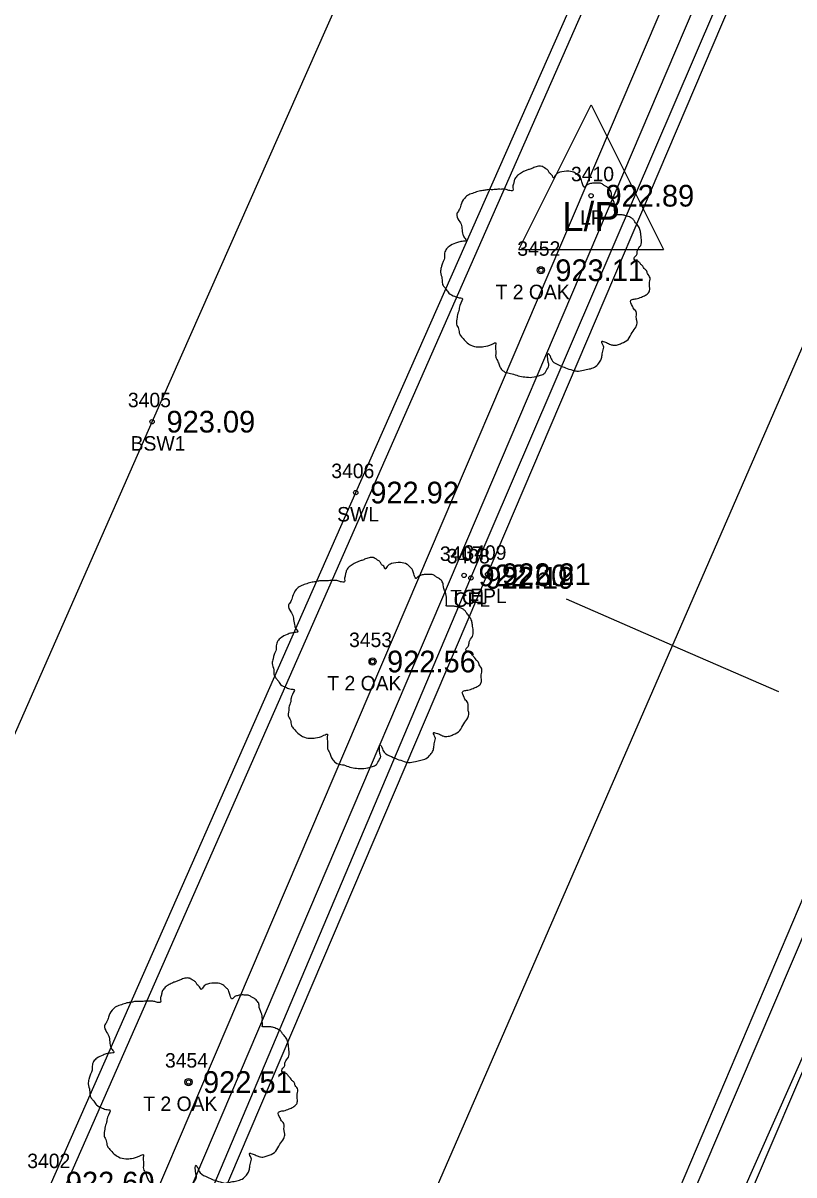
# Model space of a CAD drawing. Extents: x 1575382 to 1578175, y 1099175 to 1101955.
# Drawn here: x 1577107.7 to 1577161, y 1100867.9 to 1100947.5 of the extents above; entities that cross this region are included whole.
import ezdxf

# ---------------------------------------------------------------- set-up
doc = ezdxf.new("R2010")
doc.units = 0
for name, color, linetype in [('RD_EX_Conc', 7, 'Continuous'), ('RD_EX_Conc_txCode', 7, 'Continuous'), ('RD_EX_DR_Pipe', 7, 'Continuous'), ('RD_EX_Road', 7, 'Continuous'), ('RD_EX_Road_txCode', 7, 'Continuous'), ('RD_EX_TX_Conc_ELEV', 7, 'Continuous'), ('RD_EX_TX_Road_ELEV', 7, 'Continuous'), ('RD_EX_TX_UT_ELEV', 7, 'Continuous'), ('RD_EX_TX_VEG_ELEV', 7, 'Continuous'), ('RD_EX_UT', 7, 'Continuous'), ('RD_EX_UT_txCode', 7, 'Continuous'), ('RD_EX_VEG', 7, 'Continuous'), ('RD_EX_VEG_txCode', 7, 'Continuous'), ('RD_HC_Cl', 7, 'Continuous'), ('RD_HC_Data_Tic', 7, 'Continuous'), ('RD_SMD_Locator', 7, 'Continuous')]:
    doc.layers.add(name, color=color, linetype=linetype)

msp = doc.modelspace()

# ---------------------------------------------------------------- linework, layer by layer
at = {"layer": 'RD_EX_Conc'}
for points in [[(1577067.37, 1100812.254), (1577083.485, 1100844.878), (1577096.643, 1100874.508), (1577116.651, 1100919.942), (1577136.82, 1100965.443), (1577156.654, 1101010.405), (1577183.297, 1101070.643)], [(1577079.252, 1100805.075), (1577097.111, 1100838.835), (1577109.69, 1100867.343), (1577130.743, 1100915.042), (1577150.176, 1100959.002), (1577170.082, 1101003.92), (1577196.775, 1101064.656), (1577202.486, 1101060.003)], [(1577107.978, 1100836.943), (1577119.094, 1100862.854), (1577138.707, 1100909.145), (1577158.456, 1100955.145), (1577177.696, 1100999.964), (1577190.709, 1101030.459)], [(1577129.98, 1100812.481), (1577147.365, 1100850.909), (1577167.052, 1100896.938), (1577173.888, 1100913.381)], [(1577132.717, 1100811.321), (1577150.445, 1100848.795), (1577170.285, 1100895.209), (1577174.895, 1100906.424), (1577174.458, 1100913.152)]]:
    msp.add_lwpolyline(points, dxfattribs=at)
at = {"layer": 'RD_EX_DR_Pipe'}
for points in [[(1577226.312, 1101118.81), (1577219.842, 1101092.631), (1577219.842, 1101092.631), (1577205.279, 1101049.599), (1577205.279, 1101049.599), (1577188.031, 1101033.131), (1577188.031, 1101033.131), (1577101.879, 1100831.452)], [(1577139.994, 1100787.337), (1577129.779, 1100804.197), (1577129.779, 1100804.197), (1577232.824, 1101036.463), (1577232.824, 1101036.463), (1577240.152, 1101052.982)]]:
    msp.add_lwpolyline(points, dxfattribs=at)
at = {"layer": 'RD_EX_Road'}
for points in [[(1577060.606, 1100805.432), (1577075.531, 1100798.536), (1577081.931, 1100797.671), (1577087.923, 1100798.374), (1577091.212, 1100799.398), (1577094.487, 1100804.268), (1577106.896, 1100832.158), (1577119.895, 1100862.619), (1577139.857, 1100909.397), (1577159.206, 1100954.774), (1577178.498, 1100999.731), (1577192.432, 1101032.313), (1577206.431, 1101064.716)], [(1577078.765, 1100718.331), (1577101.643, 1100758.923), (1577113.339, 1100780.089), (1577125.29, 1100804.69), (1577146.474, 1100851.246), (1577166.057, 1100897.319), (1577205.167, 1100988.676), (1577222.285, 1101028.955), (1577224.552, 1101032.022), (1577228.298, 1101034.471), (1577233.178, 1101036.099), (1577233.178, 1101036.099), (1577237.423, 1101035.839), (1577245.428, 1101032.846), (1577248.283, 1101031.553), (1577256.851, 1101026.156), (1577298.2, 1100997.596), (1577319.207, 1100982.295), (1577334.075, 1100971.377)]]:
    msp.add_lwpolyline(points, dxfattribs=at)
at = {"layer": 'RD_EX_UT'}
for p, q in [((1577142.014, 1100931.838), (1577147.014, 1100941.838)), ((1577147.014, 1100941.838), (1577152.014, 1100931.838)), ((1577142.014, 1100931.838), (1577152.014, 1100931.838))]:
    msp.add_line(p, q, dxfattribs=at)
at = {"layer": 'RD_EX_VEG'}
msp.add_lwpolyline([(1577107.032, 1100838.114), (1577102.407, 1100840.005), (1577098.784, 1100830.652), (1577102.641, 1100828.563), (1577091.872, 1100804.274), (1577078.023, 1100800.1), (1577101.108, 1100845.444), (1577197.024, 1101063.208), (1577201.438, 1101059.636), (1577191.641, 1101036.576), (1577187.356, 1101037.816), (1577185.071, 1101032.424), (1577189.095, 1101030.587), (1577107.032, 1100838.114)], dxfattribs=at)
for centre, radius in [((1577143.545, 1100930.411), 0.25), ((1577143.532, 1100930.392), 0.0001), ((1577131.908, 1100903.363), 0.25), ((1577131.896, 1100903.344), 0.0001), ((1577119.176, 1100874.292), 0.25), ((1577119.164, 1100874.273), 0.0001)]:
    msp.add_circle(centre, radius, dxfattribs=at)
for points in [[(1577143.677, 1100937.579), (1577143.377, 1100937.604), (1577143.052, 1100937.504), (1577142.802, 1100937.404), (1577142.577, 1100937.329), (1577142.352, 1100937.229), (1577142.052, 1100937.054), (1577141.827, 1100936.854), (1577141.702, 1100936.604), (1577141.652, 1100936.379), (1577141.602, 1100936.104), (1577141.602, 1100935.929), (1577141.478, 1100935.904), (1577141.328, 1100935.929), (1577141.078, 1100936.004), (1577140.828, 1100936.004), (1577140.578, 1100936.004), (1577140.228, 1100935.979), (1577139.878, 1100935.979), (1577139.603, 1100935.929), (1577139.278, 1100935.879), (1577138.904, 1100935.754), (1577138.554, 1100935.629), (1577138.254, 1100935.379), (1577138.004, 1100934.905), (1577137.879, 1100934.555), (1577137.729, 1100934.305), (1577137.879, 1100933.855), (1577138.054, 1100933.505), (1577138.079, 1100933.305), (1577138.154, 1100932.881), (1577138.254, 1100932.656), (1577138.379, 1100932.456), (1577138.304, 1100932.431), (1577137.929, 1100932.381), (1577137.629, 1100932.281), (1577137.204, 1100932.056), (1577136.979, 1100931.831), (1577136.879, 1100931.506), (1577136.855, 1100931.156), (1577136.755, 1100930.956), (1577136.68, 1100930.682), (1577136.655, 1100930.607), (1577136.605, 1100930.282), (1577136.705, 1100929.832), (1577136.73, 1100929.482), (1577136.855, 1100929.257), (1577137.004, 1100929.082), (1577137.179, 1100928.832), (1577137.579, 1100928.607), (1577137.904, 1100928.507), (1577138.104, 1100928.483), (1577137.929, 1100927.983), (1577137.879, 1100927.633), (1577137.754, 1100927.233), (1577137.754, 1100927.158), (1577137.704, 1100926.683), (1577137.854, 1100926.358), (1577137.929, 1100925.984), (1577138.104, 1100925.759), (1577138.379, 1100925.459), (1577138.704, 1100925.234), (1577139.204, 1100925.109), (1577139.603, 1100925.134), (1577140.178, 1100925.309), (1577140.428, 1100925.384), (1577140.403, 1100925.209), (1577140.428, 1100924.834), (1577140.428, 1100924.409), (1577140.578, 1100924.084), (1577140.678, 1100923.81), (1577140.828, 1100923.56), (1577141.153, 1100923.335), (1577141.552, 1100923.26), (1577141.977, 1100923.11), (1577142.427, 1100923.035), (1577142.927, 1100923.01), (1577143.527, 1100923.16), (1577143.801, 1100923.285), (1577143.901, 1100923.46), (1577144.101, 1100923.835), (1577144.051, 1100924.059), (1577144.076, 1100924.659), (1577144.176, 1100924.484), (1577144.351, 1100924.134), (1577144.851, 1100923.835), (1577145.251, 1100923.66), (1577145.726, 1100923.51), (1577146.026, 1100923.435), (1577146.5, 1100923.51), (1577146.875, 1100923.585), (1577147.25, 1100923.71), (1577147.55, 1100923.984), (1577147.725, 1100924.259), (1577147.775, 1100924.534), (1577147.85, 1100924.909), (1577147.9, 1100925.084)], [(1577147.9, 1100925.084), (1577147.825, 1100925.259), (1577147.775, 1100925.509), (1577147.85, 1100925.484), (1577148.025, 1100925.434), (1577148.3, 1100925.309), (1577148.524, 1100925.234), (1577148.849, 1100925.259), (1577149.124, 1100925.359), (1577149.574, 1100925.634), (1577149.849, 1100926.109), (1577150.124, 1100926.508), (1577150.199, 1100926.833), (1577150.149, 1100927.058), (1577150.124, 1100927.558), (1577149.924, 1100927.808), (1577149.874, 1100927.933), (1577149.774, 1100928.333), (1577149.849, 1100928.383), (1577150.124, 1100928.433), (1577150.499, 1100928.557), (1577150.773, 1100928.682), (1577150.998, 1100928.857), (1577151.073, 1100929.082), (1577151.048, 1100929.482), (1577151.098, 1100929.882), (1577151.023, 1100930.032), (1577150.923, 1100930.182), (1577150.848, 1100930.382), (1577150.698, 1100930.532), (1577150.599, 1100930.682), (1577150.499, 1100930.781), (1577150.374, 1100930.931), (1577150.199, 1100931.056), (1577150.049, 1100931.106), (1577149.999, 1100931.256), (1577150.149, 1100931.456), (1577150.199, 1100931.556), (1577150.224, 1100931.781), (1577150.449, 1100932.131), (1577150.499, 1100932.531), (1577150.449, 1100932.956), (1577150.399, 1100933.23), (1577150.249, 1100933.505), (1577150.049, 1100933.755), (1577149.924, 1100933.93), (1577149.749, 1100934.055), (1577149.424, 1100934.18), (1577149.174, 1100934.23), (1577148.824, 1100934.23), (1577148.624, 1100934.28), (1577148.649, 1100934.33), (1577148.649, 1100934.48), (1577148.649, 1100934.755), (1577148.574, 1100935.205), (1577148.424, 1100935.704), (1577148.424, 1100935.729), (1577148.324, 1100935.979), (1577148.1, 1100936.179), (1577147.925, 1100936.279), (1577147.725, 1100936.404), (1577147.475, 1100936.429), (1577147.175, 1100936.429), (1577146.9, 1100936.379), (1577146.7, 1100936.279), (1577146.525, 1100936.154), (1577146.45, 1100936.304), (1577146.35, 1100936.604), (1577146.3, 1100936.754), (1577146.15, 1100936.929), (1577145.926, 1100937.129), (1577145.476, 1100937.254), (1577144.851, 1100937.179), (1577144.551, 1100936.979), (1577144.401, 1100936.804), (1577144.351, 1100936.929), (1577144.151, 1100937.129), (1577144.051, 1100937.304), (1577143.876, 1100937.429), (1577143.727, 1100937.529), (1577143.627, 1100937.579)], [(1577132.04, 1100910.53), (1577131.74, 1100910.555), (1577131.416, 1100910.455), (1577131.166, 1100910.355), (1577130.941, 1100910.28), (1577130.716, 1100910.18), (1577130.416, 1100910.005), (1577130.191, 1100909.806), (1577130.066, 1100909.556), (1577130.016, 1100909.331), (1577129.966, 1100909.056), (1577129.966, 1100908.881), (1577129.841, 1100908.856), (1577129.691, 1100908.881), (1577129.441, 1100908.956), (1577129.192, 1100908.956), (1577128.942, 1100908.956), (1577128.592, 1100908.931), (1577128.242, 1100908.931), (1577127.967, 1100908.881), (1577127.642, 1100908.831), (1577127.267, 1100908.706), (1577126.918, 1100908.581), (1577126.618, 1100908.331), (1577126.368, 1100907.856), (1577126.243, 1100907.507), (1577126.093, 1100907.257), (1577126.243, 1100906.807), (1577126.418, 1100906.457), (1577126.443, 1100906.257), (1577126.518, 1100905.832), (1577126.618, 1100905.607), (1577126.743, 1100905.407), (1577126.668, 1100905.383), (1577126.293, 1100905.333), (1577125.993, 1100905.233), (1577125.568, 1100905.008), (1577125.343, 1100904.783), (1577125.243, 1100904.458), (1577125.218, 1100904.108), (1577125.118, 1100903.908), (1577125.043, 1100903.633), (1577125.018, 1100903.558), (1577124.968, 1100903.233), (1577125.068, 1100902.784), (1577125.093, 1100902.434), (1577125.218, 1100902.209), (1577125.368, 1100902.034), (1577125.543, 1100901.784), (1577125.943, 1100901.559), (1577126.268, 1100901.459), (1577126.468, 1100901.434), (1577126.293, 1100900.934), (1577126.243, 1100900.585), (1577126.118, 1100900.185), (1577126.118, 1100900.11), (1577126.068, 1100899.635), (1577126.218, 1100899.31), (1577126.293, 1100898.935), (1577126.468, 1100898.71), (1577126.743, 1100898.41), (1577127.067, 1100898.186), (1577127.567, 1100898.061), (1577127.967, 1100898.086), (1577128.542, 1100898.261), (1577128.792, 1100898.336), (1577128.767, 1100898.161), (1577128.792, 1100897.786), (1577128.792, 1100897.361), (1577128.942, 1100897.036), (1577129.042, 1100896.761), (1577129.192, 1100896.511), (1577129.516, 1100896.286), (1577129.916, 1100896.211), (1577130.341, 1100896.062), (1577130.791, 1100895.987), (1577131.291, 1100895.962), (1577131.89, 1100896.111), (1577132.165, 1100896.236), (1577132.265, 1100896.411), (1577132.465, 1100896.786), (1577132.415, 1100897.011), (1577132.44, 1100897.611), (1577132.54, 1100897.436), (1577132.715, 1100897.086), (1577133.215, 1100896.786), (1577133.615, 1100896.611), (1577134.089, 1100896.461), (1577134.389, 1100896.386), (1577134.864, 1100896.461), (1577135.239, 1100896.536), (1577135.614, 1100896.661), (1577135.914, 1100896.936), (1577136.089, 1100897.211), (1577136.139, 1100897.486), (1577136.213, 1100897.861), (1577136.263, 1100898.036)], [(1577136.263, 1100898.036), (1577136.189, 1100898.211), (1577136.139, 1100898.461), (1577136.213, 1100898.435), (1577136.388, 1100898.386), (1577136.663, 1100898.261), (1577136.888, 1100898.186), (1577137.213, 1100898.211), (1577137.488, 1100898.311), (1577137.938, 1100898.586), (1577138.213, 1100899.06), (1577138.487, 1100899.46), (1577138.562, 1100899.785), (1577138.512, 1100900.01), (1577138.487, 1100900.51), (1577138.288, 1100900.759), (1577138.238, 1100900.884), (1577138.138, 1100901.284), (1577138.213, 1100901.334), (1577138.487, 1100901.384), (1577138.862, 1100901.509), (1577139.137, 1100901.634), (1577139.362, 1100901.809), (1577139.437, 1100902.034), (1577139.412, 1100902.434), (1577139.462, 1100902.834), (1577139.387, 1100902.984), (1577139.287, 1100903.133), (1577139.212, 1100903.333), (1577139.062, 1100903.483), (1577138.962, 1100903.633), (1577138.862, 1100903.733), (1577138.737, 1100903.883), (1577138.562, 1100904.008), (1577138.413, 1100904.058), (1577138.363, 1100904.208), (1577138.512, 1100904.408), (1577138.562, 1100904.508), (1577138.587, 1100904.733), (1577138.812, 1100905.083), (1577138.862, 1100905.482), (1577138.812, 1100905.907), (1577138.762, 1100906.182), (1577138.612, 1100906.457), (1577138.413, 1100906.707), (1577138.288, 1100906.882), (1577138.113, 1100907.007), (1577137.788, 1100907.132), (1577137.538, 1100907.182), (1577137.188, 1100907.182), (1577136.988, 1100907.232), (1577137.013, 1100907.282), (1577137.013, 1100907.432), (1577137.013, 1100907.707), (1577136.938, 1100908.156), (1577136.788, 1100908.656), (1577136.788, 1100908.681), (1577136.688, 1100908.931), (1577136.463, 1100909.131), (1577136.288, 1100909.231), (1577136.089, 1100909.356), (1577135.839, 1100909.381), (1577135.539, 1100909.381), (1577135.264, 1100909.331), (1577135.064, 1100909.231), (1577134.889, 1100909.106), (1577134.814, 1100909.256), (1577134.714, 1100909.556), (1577134.664, 1100909.706), (1577134.514, 1100909.88), (1577134.289, 1100910.08), (1577133.839, 1100910.205), (1577133.215, 1100910.13), (1577132.915, 1100909.931), (1577132.765, 1100909.756), (1577132.715, 1100909.88), (1577132.515, 1100910.08), (1577132.415, 1100910.255), (1577132.24, 1100910.38), (1577132.09, 1100910.48), (1577131.99, 1100910.53)], [(1577119.308, 1100881.459), (1577119.008, 1100881.484), (1577118.684, 1100881.384), (1577118.434, 1100881.284), (1577118.209, 1100881.209), (1577117.984, 1100881.109), (1577117.684, 1100880.934), (1577117.459, 1100880.734), (1577117.334, 1100880.484), (1577117.284, 1100880.259), (1577117.234, 1100879.985), (1577117.234, 1100879.81), (1577117.109, 1100879.785), (1577116.959, 1100879.81), (1577116.709, 1100879.885), (1577116.459, 1100879.885), (1577116.21, 1100879.885), (1577115.86, 1100879.86), (1577115.51, 1100879.86), (1577115.235, 1100879.81), (1577114.91, 1100879.76), (1577114.535, 1100879.635), (1577114.185, 1100879.51), (1577113.886, 1100879.26), (1577113.636, 1100878.785), (1577113.511, 1100878.435), (1577113.361, 1100878.185), (1577113.511, 1100877.736), (1577113.686, 1100877.386), (1577113.711, 1100877.186), (1577113.786, 1100876.761), (1577113.886, 1100876.536), (1577114.011, 1100876.336), (1577113.936, 1100876.311), (1577113.561, 1100876.261), (1577113.261, 1100876.161), (1577112.836, 1100875.936), (1577112.611, 1100875.711), (1577112.511, 1100875.387), (1577112.486, 1100875.037), (1577112.386, 1100874.837), (1577112.311, 1100874.562), (1577112.286, 1100874.487), (1577112.236, 1100874.162), (1577112.336, 1100873.712), (1577112.361, 1100873.362), (1577112.486, 1100873.138), (1577112.636, 1100872.963), (1577112.811, 1100872.713), (1577113.211, 1100872.488), (1577113.536, 1100872.388), (1577113.736, 1100872.363), (1577113.561, 1100871.863), (1577113.511, 1100871.513), (1577113.386, 1100871.113), (1577113.386, 1100871.039), (1577113.336, 1100870.564), (1577113.486, 1100870.239), (1577113.561, 1100869.864), (1577113.736, 1100869.639), (1577114.011, 1100869.339), (1577114.335, 1100869.114), (1577114.835, 1100868.989), (1577115.235, 1100869.014), (1577115.81, 1100869.189), (1577116.06, 1100869.264), (1577116.035, 1100869.089), (1577116.06, 1100868.714), (1577116.06, 1100868.29), (1577116.21, 1100867.965), (1577116.31, 1100867.69), (1577116.459, 1100867.44), (1577116.784, 1100867.215), (1577117.184, 1100867.14), (1577117.609, 1100866.99), (1577118.059, 1100866.915), (1577118.559, 1100866.89), (1577119.158, 1100867.04), (1577119.433, 1100867.165), (1577119.533, 1100867.34), (1577119.733, 1100867.715), (1577119.683, 1100867.94), (1577119.708, 1100868.54), (1577119.808, 1100868.365), (1577119.983, 1100868.015), (1577120.483, 1100867.715), (1577120.883, 1100867.54), (1577121.357, 1100867.39), (1577121.657, 1100867.315), (1577122.132, 1100867.39), (1577122.507, 1100867.465), (1577122.882, 1100867.59), (1577123.182, 1100867.865), (1577123.356, 1100868.14), (1577123.406, 1100868.415), (1577123.481, 1100868.789), (1577123.531, 1100868.964)], [(1577123.531, 1100868.964), (1577123.456, 1100869.139), (1577123.406, 1100869.389), (1577123.481, 1100869.364), (1577123.656, 1100869.314), (1577123.931, 1100869.189), (1577124.156, 1100869.114), (1577124.481, 1100869.139), (1577124.756, 1100869.239), (1577125.206, 1100869.514), (1577125.481, 1100869.989), (1577125.755, 1100870.389), (1577125.83, 1100870.714), (1577125.78, 1100870.939), (1577125.755, 1100871.438), (1577125.555, 1100871.688), (1577125.505, 1100871.813), (1577125.406, 1100872.213), (1577125.481, 1100872.263), (1577125.755, 1100872.313), (1577126.13, 1100872.438), (1577126.405, 1100872.563), (1577126.63, 1100872.738), (1577126.705, 1100872.963), (1577126.68, 1100873.362), (1577126.73, 1100873.762), (1577126.655, 1100873.912), (1577126.555, 1100874.062), (1577126.48, 1100874.262), (1577126.33, 1100874.412), (1577126.23, 1100874.562), (1577126.13, 1100874.662), (1577126.005, 1100874.812), (1577125.83, 1100874.937), (1577125.68, 1100874.987), (1577125.63, 1100875.137), (1577125.78, 1100875.337), (1577125.83, 1100875.437), (1577125.855, 1100875.661), (1577126.08, 1100876.011), (1577126.13, 1100876.411), (1577126.08, 1100876.836), (1577126.03, 1100877.111), (1577125.88, 1100877.386), (1577125.68, 1100877.636), (1577125.555, 1100877.811), (1577125.381, 1100877.935), (1577125.056, 1100878.06), (1577124.806, 1100878.11), (1577124.456, 1100878.11), (1577124.256, 1100878.16), (1577124.281, 1100878.21), (1577124.281, 1100878.36), (1577124.281, 1100878.635), (1577124.206, 1100879.085), (1577124.056, 1100879.585), (1577124.056, 1100879.61), (1577123.956, 1100879.86), (1577123.731, 1100880.06), (1577123.556, 1100880.159), (1577123.356, 1100880.284), (1577123.107, 1100880.309), (1577122.807, 1100880.309), (1577122.532, 1100880.259), (1577122.332, 1100880.159), (1577122.157, 1100880.035), (1577122.082, 1100880.184), (1577121.982, 1100880.484), (1577121.932, 1100880.634), (1577121.782, 1100880.809), (1577121.557, 1100881.009), (1577121.107, 1100881.134), (1577120.483, 1100881.059), (1577120.183, 1100880.859), (1577120.033, 1100880.684), (1577119.983, 1100880.809), (1577119.783, 1100881.009), (1577119.683, 1100881.184), (1577119.508, 1100881.309), (1577119.358, 1100881.409), (1577119.258, 1100881.459)]]:
    msp.add_spline(points, degree=3, dxfattribs=at)
at = {"layer": 'RD_HC_Cl'}
msp.add_line((1577114.032, 1100815.757), (1577364.891, 1101392.08), dxfattribs=at)
at = {"layer": 'RD_HC_Data_Tic'}
for q in [(1577145.315, 1100907.672), (1577159.986, 1100901.286)]:
    msp.add_line((1577152.651, 1100904.479), q, dxfattribs=at)
at = {"layer": 'RD_SMD_Locator'}
for centre in [(1577147.014, 1100935.562), (1577143.545, 1100930.411), (1577116.651, 1100919.942), (1577130.743, 1100915.042), (1577138.229, 1100909.317), (1577139.857, 1100909.397), (1577138.707, 1100909.145), (1577131.908, 1100903.363), (1577119.176, 1100874.292)]:
    msp.add_circle(centre, 0.15, dxfattribs=at)

# ---------------------------------------------------------------- texts
at = {"layer": 'RD_EX_Conc_txCode'}
for s, p in [('3405', (1577114.982, 1100920.942)), ('BSW1', (1577115.171, 1100917.942)), ('3406', (1577129.05, 1100916.042)), ('SWL', (1577129.451, 1100913.042)), ('3407', (1577136.56, 1100910.317)), ('3408', (1577137.038, 1100910.145)), ('TC1', (1577137.268, 1100907.317)), ('CFL', (1577137.502, 1100907.145)), ('3402', (1577108.021, 1100868.343))]:
    msp.add_text(s, height=1, dxfattribs=at).set_placement(p)
at = {"layer": 'RD_EX_Road_txCode'}
for s, p in [('3409', (1577138.188, 1100910.397)), ('EPL', (1577138.653, 1100907.397))]:
    msp.add_text(s, height=1, dxfattribs=at).set_placement(p)
at = {"layer": 'RD_EX_TX_Conc_ELEV'}
for s, p in [('923.09', (1577117.651, 1100919.192)), ('922.92', (1577131.743, 1100914.292)), ('922.60', (1577139.229, 1100908.567)), ('922.19', (1577139.707, 1100908.395)), ('922.60', (1577110.69, 1100866.593))]:
    msp.add_text(s, height=1.5, dxfattribs=at).set_placement(p)
at = {"layer": 'RD_EX_TX_Road_ELEV'}
msp.add_text('922.21', height=1.5, dxfattribs=at).set_placement((1577140.857, 1100908.647))
at = {"layer": 'RD_EX_TX_UT_ELEV'}
msp.add_text('922.89', height=1.5, dxfattribs=at).set_placement((1577148.014, 1100934.812))
at = {"layer": 'RD_EX_TX_VEG_ELEV'}
for s, p in [('923.11', (1577144.545, 1100929.661)), ('922.56', (1577132.908, 1100902.613)), ('922.51', (1577120.176, 1100873.542))]:
    msp.add_text(s, height=1.5, dxfattribs=at).set_placement(p)
at = {"layer": 'RD_EX_UT'}
msp.add_text('L/P', height=2, dxfattribs=at).set_placement((1577145.006, 1100933.12))
at = {"layer": 'RD_EX_UT_txCode'}
for s, p in [('3410', (1577145.628, 1100936.562)), ('LP', (1577146.258, 1100933.562))]:
    msp.add_text(s, height=1, dxfattribs=at).set_placement(p)
at = {"layer": 'RD_EX_VEG_txCode'}
for s, p in [('3452', (1577141.915, 1100931.411)), ('T 2 OAK', (1577140.411, 1100928.411)), ('3453', (1577130.278, 1100904.363)), ('T 2 OAK', (1577128.775, 1100901.363)), ('3454', (1577117.546, 1100875.292)), ('T 2 OAK', (1577116.042, 1100872.292))]:
    msp.add_text(s, height=1, dxfattribs=at).set_placement(p)

doc.saveas('drawing.dxf')
